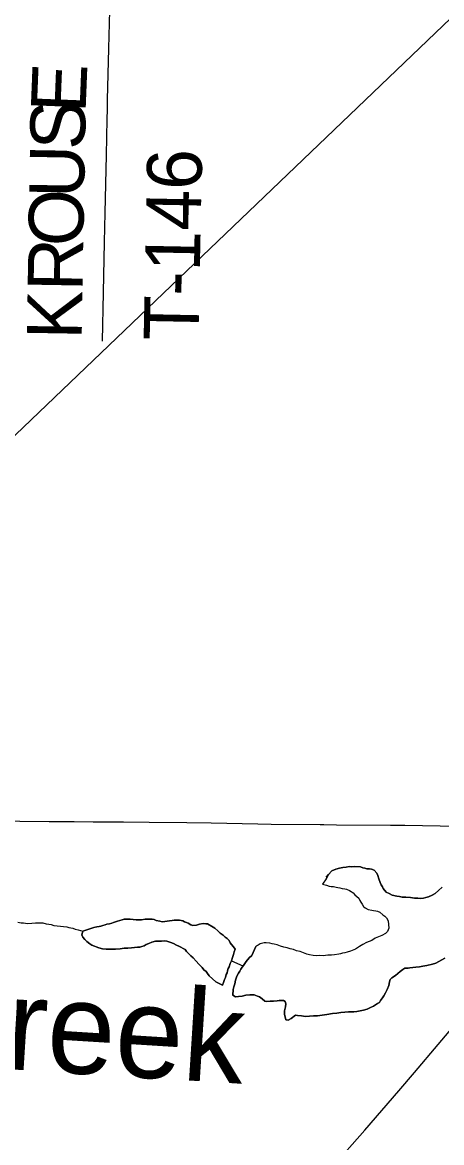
# Model space of a CAD drawing. Extents: x -483 to 680, y 0 to 440.
# Drawn here: x 121.8 to 143.5, y 160.9 to 218.9 of the extents above; entities that cross this region are included whole.
import ezdxf

# ---------------------------------------------------------------- set-up
doc = ezdxf.new("R2010")
doc.units = 0
for name, color, linetype in [('GM_X_Minor_Lake', 7, 'Continuous'), ('GM_X_Minor_River', 7, 'Continuous'), ('GM_X_Minor_River_Text', 7, 'Continuous'), ('GM_X_State_Route', 7, 'Continuous'), ('GM_X_Township_Road', 7, 'Continuous'), ('GM_X_Township_Road_Text', 7, 'Continuous')]:
    doc.layers.add(name, color=color, linetype=linetype)

msp = doc.modelspace()

# ---------------------------------------------------------------- linework, layer by layer
at = {"layer": 'GM_X_Minor_Lake'}
for points in [[(143.574, 174.106), (143.378, 173.941), (143.202, 173.795), (143.047, 173.705), (142.854, 173.616), (142.719, 173.583), (142.604, 173.549), (142.47, 173.534), (142.299, 173.54), (142.128, 173.545), (141.919, 173.571), (141.692, 173.598), (141.501, 173.604), (141.35, 173.628), (141.217, 173.652), (140.971, 173.698), (140.821, 173.779), (140.672, 173.86), (140.506, 174.037), (140.471, 174.133), (140.417, 174.23), (140.364, 174.365), (140.293, 174.538), (140.242, 174.711), (140.189, 174.846), (140.042, 175.004), (139.91, 175.046), (139.796, 175.069), (139.663, 175.073), (139.568, 175.095), (139.455, 175.118), (139.342, 175.16), (139.019, 175.19), (138.867, 175.176), (138.752, 175.18), (138.599, 175.147), (138.427, 175.133), (138.255, 175.101), (138.063, 175.05), (137.85, 174.962), (137.673, 174.778), (137.554, 174.63), (137.673, 174.778), (137.552, 174.554)], [(137.552, 174.554), (137.673, 174.778), (137.554, 174.63), (137.673, 174.778), (137.85, 174.962), (138.063, 175.05), (138.255, 175.101), (138.427, 175.133), (138.599, 175.147), (138.752, 175.18), (138.867, 175.176), (139.019, 175.19), (139.342, 175.16), (139.455, 175.118), (139.568, 175.095), (139.663, 175.073), (139.796, 175.069), (139.91, 175.046), (140.042, 175.004), (140.189, 174.846), (140.242, 174.711), (140.293, 174.538), (140.364, 174.365), (140.417, 174.23), (140.471, 174.133), (140.506, 174.037), (140.672, 173.86), (140.821, 173.779), (140.971, 173.698), (141.217, 173.652), (141.35, 173.628), (141.501, 173.604), (141.692, 173.598), (141.919, 173.571), (142.128, 173.545), (142.299, 173.54), (142.47, 173.534), (142.604, 173.549), (142.719, 173.583), (142.854, 173.616), (143.047, 173.705), (143.202, 173.795), (143.378, 173.941), (143.574, 174.106)], [(137.552, 174.554), (137.372, 174.274), (137.579, 174.21), (137.711, 174.168), (137.824, 174.145), (137.938, 174.141), (138.071, 174.118), (138.165, 174.096), (138.26, 174.074), (138.393, 174.05), (138.525, 174.027), (138.62, 174.005), (138.77, 173.942), (138.863, 173.882), (138.957, 173.822), (139.049, 173.724), (139.141, 173.626), (139.252, 173.546), (139.306, 173.43), (139.36, 173.333), (139.433, 173.236), (139.486, 173.12), (139.579, 173.041), (139.729, 172.959), (139.918, 172.915), (140.013, 172.912), (140.126, 172.889), (140.221, 172.867), (140.334, 172.825), (140.501, 172.686), (140.593, 172.607), (140.686, 172.528), (140.776, 172.373), (140.802, 171.992), (140.74, 171.822), (140.641, 171.712), (140.447, 171.604), (140.274, 171.534), (140.1, 171.463), (139.925, 171.355), (139.655, 171.25), (139.461, 171.142), (139.286, 171.034), (139.073, 170.908), (138.822, 170.802), (138.649, 170.751), (138.534, 170.717), (138.4, 170.702), (138.304, 170.667), (138.208, 170.651), (137.997, 170.601), (137.844, 170.587), (137.654, 170.594), (137.52, 170.579), (137.405, 170.564), (137.234, 170.57), (137.081, 170.556), (136.892, 170.581), (136.702, 170.606), (136.551, 170.649), (136.382, 170.712), (136.212, 170.775), (136.023, 170.819), (135.873, 170.881), (135.703, 170.925), (135.533, 170.969), (135.363, 171.012), (135.193, 171.056), (135.024, 171.119), (134.873, 171.162), (134.759, 171.185), (134.646, 171.207), (134.456, 171.233), (134.342, 171.237), (134.15, 171.186), (134.033, 171.114), (133.936, 171.06), (133.917, 171.042)], [(137.552, 174.554), (137.372, 174.274), (137.579, 174.21), (137.711, 174.168), (137.824, 174.145), (137.938, 174.141), (138.071, 174.118), (138.165, 174.096), (138.26, 174.074), (138.393, 174.05), (138.525, 174.027), (138.62, 174.005), (138.77, 173.942), (138.863, 173.882), (138.957, 173.822), (139.049, 173.724), (139.141, 173.626), (139.252, 173.546), (139.306, 173.43), (139.36, 173.333), (139.433, 173.236), (139.486, 173.12), (139.579, 173.041), (139.729, 172.959), (139.918, 172.915), (140.013, 172.912), (140.126, 172.889), (140.221, 172.867), (140.334, 172.825), (140.501, 172.686), (140.593, 172.607), (140.686, 172.528), (140.776, 172.373), (140.802, 171.992), (140.74, 171.822), (140.641, 171.712), (140.447, 171.604), (140.274, 171.534), (140.1, 171.463), (139.925, 171.355), (139.655, 171.25), (139.461, 171.142), (139.286, 171.034), (139.073, 170.908), (138.822, 170.802), (138.649, 170.751), (138.534, 170.717), (138.4, 170.702), (138.304, 170.667), (138.208, 170.651), (137.997, 170.601), (137.844, 170.587), (137.654, 170.594), (137.52, 170.579), (137.405, 170.564), (137.234, 170.57), (137.081, 170.556), (136.892, 170.581), (136.702, 170.606), (136.551, 170.649), (136.382, 170.712), (136.212, 170.775), (136.023, 170.819), (135.873, 170.881), (135.703, 170.925), (135.533, 170.969), (135.363, 171.012), (135.193, 171.056), (135.024, 171.119), (134.873, 171.162), (134.759, 171.185), (134.646, 171.207), (134.456, 171.233), (134.342, 171.237), (134.15, 171.186), (134.033, 171.114), (133.936, 171.06), (133.917, 171.042)], [(128.727, 171.31), (128.88, 171.323), (129.032, 171.318), (129.184, 171.332), (129.317, 171.309), (129.524, 171.245), (129.656, 171.203), (129.806, 171.102), (129.938, 171.06), (130.031, 171), (130.162, 170.938), (130.255, 170.878), (130.328, 170.781), (130.457, 170.643), (130.55, 170.564), (130.68, 170.445), (130.827, 170.288), (130.974, 170.131), (131.14, 169.955), (131.231, 169.837), (131.342, 169.739), (131.415, 169.641), (131.507, 169.524), (131.673, 169.366), (131.84, 169.208), (132.196, 169.044), (132.239, 169.176), (132.301, 169.326), (132.342, 169.439), (132.385, 169.59), (132.426, 169.683), (132.448, 169.778), (132.49, 169.891), (132.531, 169.984), (132.593, 170.154), (132.655, 170.304), (132.718, 170.473), (132.761, 170.624), (132.803, 170.755), (132.846, 170.906), (132.755, 171.023), (132.663, 171.14), (132.59, 171.238), (132.537, 171.354), (132.426, 171.453), (132.333, 171.532), (132.222, 171.631), (132.073, 171.731), (131.943, 171.849), (131.795, 171.987), (131.702, 172.047), (131.421, 172.209), (131.326, 172.212), (131.194, 172.236), (131.002, 172.204), (130.848, 172.152), (130.657, 172.12), (130.544, 172.162), (130.413, 172.243), (130.319, 172.284), (130.225, 172.325), (130.132, 172.366), (129.962, 172.41), (129.867, 172.413), (129.695, 172.4), (129.58, 172.384), (129.446, 172.37), (129.331, 172.355), (129.198, 172.34), (129.064, 172.326), (128.95, 172.348), (128.761, 172.393), (128.648, 172.435), (128.554, 172.457), (128.364, 172.463), (128.192, 172.45), (128.001, 172.418), (127.829, 172.424), (127.715, 172.428), (127.411, 172.457), (127.316, 172.46), (127.221, 172.463), (127.106, 172.448), (126.991, 172.414), (126.876, 172.379), (126.76, 172.345), (126.645, 172.311), (126.549, 172.276), (126.452, 172.241), (126.337, 172.207), (126.203, 172.193), (126.107, 172.158), (125.992, 172.124), (125.895, 172.089), (125.8, 172.073), (125.685, 172.058), (125.531, 172.025), (124.954, 171.835)], [(124.954, 171.835), (125.531, 172.025), (125.685, 172.058), (125.8, 172.073), (125.895, 172.089), (125.992, 172.124), (126.107, 172.158), (126.203, 172.193), (126.337, 172.207), (126.452, 172.241), (126.549, 172.276), (126.645, 172.311), (126.76, 172.345), (126.876, 172.379), (126.991, 172.414), (127.106, 172.448), (127.221, 172.463), (127.316, 172.46), (127.411, 172.457), (127.715, 172.428), (127.829, 172.424), (128.001, 172.418), (128.192, 172.45), (128.364, 172.463), (128.554, 172.457), (128.648, 172.435), (128.761, 172.393), (128.95, 172.348), (129.064, 172.326), (129.198, 172.34), (129.331, 172.355), (129.446, 172.37), (129.58, 172.384), (129.695, 172.4), (129.867, 172.413), (129.962, 172.41), (130.132, 172.366), (130.225, 172.325), (130.319, 172.284), (130.413, 172.243), (130.544, 172.162), (130.657, 172.12), (130.848, 172.152), (131.002, 172.204), (131.194, 172.236), (131.326, 172.212), (131.421, 172.209), (131.702, 172.047), (131.795, 171.987), (131.943, 171.849), (132.073, 171.731), (132.222, 171.631), (132.333, 171.532), (132.426, 171.453), (132.537, 171.354), (132.59, 171.238), (132.663, 171.14), (132.755, 171.023), (132.846, 170.906), (132.803, 170.755), (132.761, 170.624), (132.718, 170.473), (132.655, 170.304), (132.593, 170.154), (132.531, 169.984), (132.49, 169.891), (132.448, 169.778), (132.426, 169.683), (132.385, 169.59), (132.342, 169.439), (132.301, 169.326), (132.239, 169.176), (132.196, 169.044), (131.84, 169.208), (131.673, 169.366), (131.507, 169.524), (131.415, 169.641), (131.342, 169.739), (131.231, 169.837), (131.14, 169.955), (130.974, 170.131), (130.827, 170.288), (130.68, 170.445), (130.55, 170.564), (130.457, 170.643), (130.328, 170.781), (130.255, 170.878), (130.162, 170.938), (130.031, 171), (129.938, 171.06), (129.806, 171.102), (129.656, 171.203), (129.524, 171.245), (129.317, 171.309), (129.184, 171.332), (129.032, 171.318), (128.88, 171.323), (128.727, 171.31)], [(124.954, 171.835), (124.933, 171.759), (124.91, 171.646), (124.963, 171.53), (125.054, 171.394), (125.165, 171.295), (125.314, 171.176), (125.426, 171.115), (125.783, 170.97), (125.972, 170.926), (126.162, 170.9), (126.333, 170.895), (126.505, 170.908), (126.657, 170.903), (126.886, 170.914), (127.097, 170.945), (127.287, 170.958), (127.478, 170.971), (127.631, 170.985), (127.784, 170.999), (127.918, 171.013), (128.014, 171.048), (128.129, 171.082), (128.245, 171.135), (128.38, 171.188), (128.535, 171.259), (128.727, 171.31)], [(128.727, 171.31), (128.535, 171.259), (128.38, 171.188), (128.245, 171.135), (128.129, 171.082), (128.014, 171.048), (127.918, 171.013), (127.784, 170.999), (127.631, 170.985), (127.478, 170.971), (127.287, 170.958), (127.097, 170.945), (126.886, 170.914), (126.657, 170.903), (126.505, 170.908), (126.333, 170.895), (126.162, 170.9), (125.972, 170.926), (125.783, 170.97), (125.426, 171.115), (125.314, 171.176), (125.165, 171.295), (125.054, 171.394), (124.963, 171.53), (124.91, 171.646), (124.933, 171.759), (124.954, 171.835)], [(133.917, 171.042), (133.711, 170.573), (133.574, 170.444), (133.416, 170.259), (133.356, 170.166), (133.276, 170.055), (133.216, 169.961), (133.137, 169.869), (133.095, 169.756), (133.016, 169.664), (132.934, 169.495), (132.87, 169.288), (132.826, 169.099), (132.783, 168.949), (132.741, 168.817), (132.731, 168.513)], [(132.731, 168.513), (132.741, 168.817), (132.783, 168.949), (132.826, 169.099), (132.87, 169.288), (132.934, 169.495), (133.016, 169.664), (133.095, 169.756), (133.137, 169.869), (133.216, 169.961), (133.276, 170.055), (133.356, 170.166), (133.416, 170.259), (133.574, 170.444), (133.711, 170.573), (133.917, 171.042)], [(132.731, 168.513), (132.862, 168.433), (133.015, 168.446), (133.206, 168.459), (133.398, 168.51), (133.608, 168.541), (133.703, 168.538), (133.837, 168.533), (134.006, 168.47), (134.1, 168.429), (134.249, 168.329), (134.379, 168.211), (134.473, 168.189), (134.664, 168.201), (134.836, 168.215), (135.026, 168.227), (135.122, 168.243), (135.217, 168.24), (135.351, 168.235), (135.444, 168.194), (135.478, 168.06), (135.454, 167.909), (135.41, 167.701), (135.406, 167.606), (135.403, 167.511), (135.438, 167.396), (135.471, 167.242), (135.585, 167.219), (135.74, 167.309), (135.974, 167.473), (136.069, 167.47), (136.277, 167.444), (136.486, 167.418), (136.696, 167.43), (136.906, 167.442), (137.115, 167.454), (137.345, 167.484), (137.593, 167.514), (137.881, 167.561), (138.11, 167.592), (138.32, 167.623), (138.53, 167.635), (138.721, 167.648), (138.988, 167.658), (139.141, 167.672), (139.313, 167.704), (139.486, 167.736), (139.678, 167.787), (139.852, 167.876), (140.007, 167.947), (140.221, 168.092), (140.318, 168.146), (140.378, 168.239), (140.478, 168.388), (140.538, 168.481), (140.638, 168.63), (140.72, 168.818), (140.803, 169.024), (140.847, 169.213), (140.87, 169.326), (140.968, 169.418), (141.143, 169.545), (141.397, 169.746), (141.534, 169.856), (141.631, 169.91), (141.803, 169.923), (141.898, 169.939), (142.051, 169.953), (142.204, 169.967), (142.395, 169.979), (142.567, 170.012), (142.778, 170.062), (143.066, 170.128), (143.239, 170.179), (143.704, 170.43)], [(143.704, 170.43), (143.239, 170.179), (143.066, 170.128), (142.778, 170.062), (142.567, 170.012), (142.395, 169.979), (142.204, 169.967), (142.051, 169.953), (141.898, 169.939), (141.803, 169.923), (141.631, 169.91), (141.534, 169.856), (141.397, 169.746), (141.143, 169.545), (140.968, 169.418), (140.87, 169.326), (140.847, 169.213), (140.803, 169.024), (140.72, 168.818), (140.638, 168.63), (140.538, 168.481), (140.478, 168.388), (140.378, 168.239), (140.318, 168.146), (140.221, 168.092), (140.007, 167.947), (139.852, 167.876), (139.678, 167.787), (139.486, 167.736), (139.313, 167.704), (139.141, 167.672), (138.988, 167.658), (138.721, 167.648), (138.53, 167.635), (138.32, 167.623), (138.11, 167.592), (137.881, 167.561), (137.593, 167.514), (137.345, 167.484), (137.115, 167.454), (136.906, 167.442), (136.696, 167.43), (136.486, 167.418), (136.277, 167.444), (136.069, 167.47), (135.974, 167.473), (135.74, 167.309), (135.585, 167.219), (135.471, 167.242), (135.438, 167.396), (135.403, 167.511), (135.406, 167.606), (135.41, 167.701), (135.454, 167.909), (135.478, 168.06), (135.444, 168.194), (135.351, 168.235), (135.217, 168.24), (135.122, 168.243), (135.026, 168.227), (134.836, 168.215), (134.664, 168.201), (134.473, 168.189), (134.379, 168.211), (134.249, 168.329), (134.1, 168.429), (134.006, 168.47), (133.837, 168.533), (133.703, 168.538), (133.608, 168.541), (133.398, 168.51), (133.206, 168.459), (133.015, 168.446), (132.862, 168.433), (132.731, 168.513)]]:
    msp.add_lwpolyline(points, dxfattribs=at)
at = {"layer": 'GM_X_Minor_River'}
msp.add_line((132.655, 170.304), (133.253, 170.032), dxfattribs=at)
for points in [[(74.642, 128.314), (75.587, 153.634), (193.508, 266.565)], [(121.599, 172.308), (121.769, 172.264), (121.883, 172.26), (122.092, 172.234), (122.32, 172.246), (122.511, 172.259), (122.74, 172.27), (122.892, 172.265), (123.062, 172.221), (123.195, 172.198), (123.327, 172.174), (123.459, 172.132), (123.63, 172.107), (124.123, 172.053), (124.237, 172.03), (124.331, 172.008), (124.445, 171.985), (124.558, 171.943), (124.709, 171.9), (124.954, 171.835)]]:
    msp.add_lwpolyline(points, dxfattribs=at)
at = {"layer": 'GM_X_State_Route'}
msp.add_lwpolyline([(137.848, 159.588), (139.558, 161.519), (141.33, 163.562), (142.134, 164.51), (144.581, 167.407)], dxfattribs=at)
at = {"layer": 'GM_X_Township_Road'}
for points in [[(126.229, 214.414), (126.237, 214.912), (126.311, 217.584), (126.376, 220.226), (126.489, 224.857), (126.539, 227.095), (126.559, 227.882)], [(125.984, 202.417), (126.025, 204.935), (126.08, 207.546), (126.114, 209.069), (126.182, 212.053), (126.222, 213.917), (126.229, 214.414)], [(100.737, 177.797), (100.977, 177.829), (101.19, 177.862), (101.458, 177.904), (101.808, 177.936), (102.087, 177.941), (102.522, 177.93), (109.434, 177.72), (110.254, 177.698), (111.466, 177.677), (114.605, 177.627), (118.335, 177.576), (120.262, 177.549), (121.692, 177.538), (123.215, 177.526), (124.516, 177.514), (125.497, 177.506), (127.069, 177.498), (128.397, 177.48), (130.345, 177.458), (131.603, 177.441), (134.027, 177.391), (134.711, 177.379), (137.241, 177.361)], [(137.241, 177.361), (137.444, 177.36), (138.097, 177.353), (140.893, 177.327), (141.638, 177.323), (143.471, 177.287), (145.118, 177.26), (145.832, 177.255), (146.142, 177.254), (146.609, 177.249), (147.417, 177.248), (148.535, 177.237), (149.623, 177.227), (150.244, 177.218), (151.141, 177.189), (151.623, 177.174)]]:
    msp.add_lwpolyline(points, dxfattribs=at)

# ---------------------------------------------------------------- texts
at = {"layer": 'GM_X_Minor_River_Text'}
msp.add_text('Creek', height=4.7372, rotation=356.41895, dxfattribs=at).set_placement((116.329, 164.979))
at = {"layer": 'GM_X_Township_Road_Text'}
for s, height, rotation, p in [('E', 2.841, 87.75375, (125.098, 214.215)), ('S', 2.841, 88.86905, (125.061, 212.313)), ('U', 2.841, 89.04186, (125.019, 209.816)), ('T-146', 2.8409, 88.87633, (130.946, 202.421)), ('O', 2.841, 89.04187, (124.977, 207.316)), ('R', 2.841, 89.04359, (124.938, 204.983)), ('K', 2.841, 89.04187, (124.897, 202.484))]:
    msp.add_text(s, height=height, rotation=rotation, dxfattribs=at).set_placement(p)

doc.saveas('drawing.dxf')
